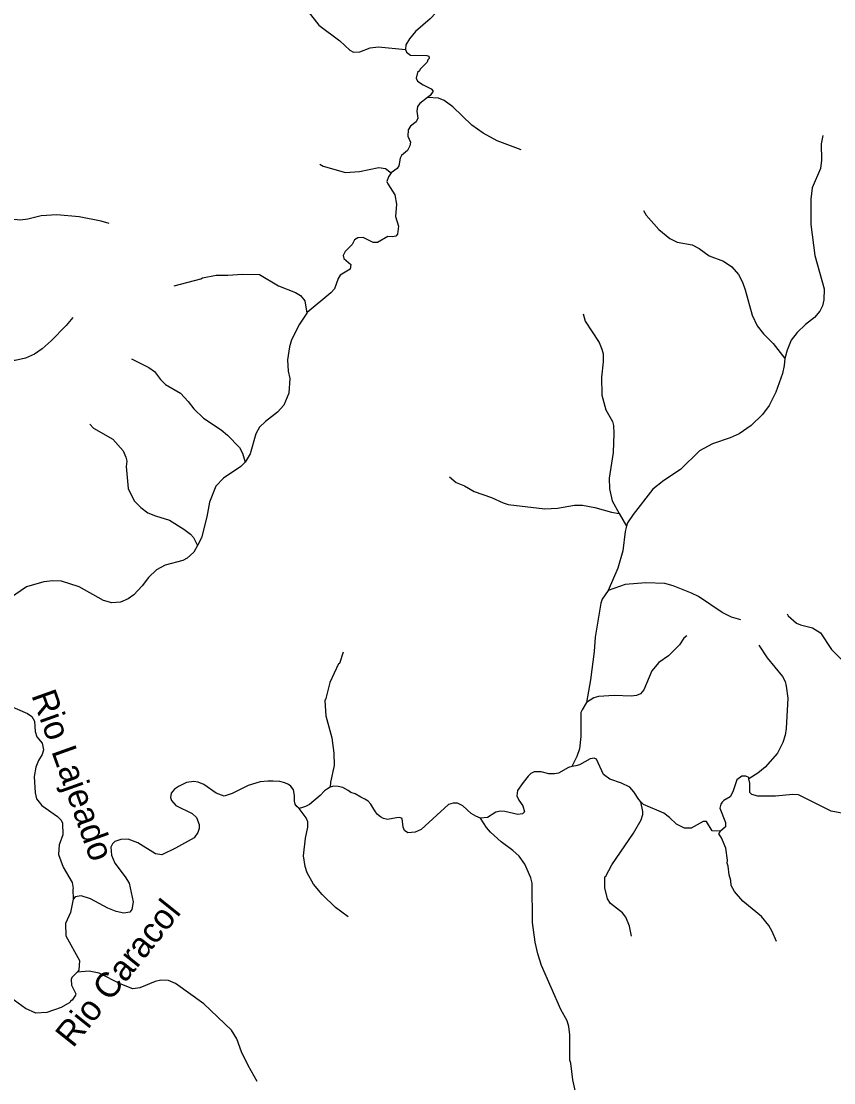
# Model space of a CAD drawing. Extents: x 280.4 to 335.6, y 8893.9 to 8949.5.
# Drawn here: x 309.86 to 316.37, y 8901.25 to 8909.74 of the extents above; entities that cross this region are included whole.
import ezdxf
from ezdxf.enums import TextEntityAlignment as Align

# ---------------------------------------------------------------- set-up
doc = ezdxf.new("R2010")
doc.units = 0
doc.header["$LTSCALE"] = 0.064
doc.layers.add('61', color=7, linetype='Continuous')
doc.layers.add('7', color=7, linetype='Continuous', lineweight=25)

msp = doc.modelspace()

# ---------------------------------------------------------------- linework, layer by layer
at = {"layer": '7'}
msp.add_line((314.649, 8905.8038), (314.7074, 8905.7013), dxfattribs=at)
for points in [[(313.2777, 8909.9961), (313.275, 8909.978), (313.25, 8909.9355), (313.2249, 8909.9078), (313.2207, 8909.8915), (313.2144, 8909.8897), (313.211, 8909.8641), (313.1829, 8909.8126), (313.136, 8909.7596), (313.0193, 8909.6603), (312.969, 8909.6008), (312.9395, 8909.5529), (312.9378, 8909.5154)], [(312.1598, 8909.8191), (312.2456, 8909.7111), (312.4115, 8909.5851), (312.4922, 8909.5097), (312.5214, 8909.4927), (312.5734, 8909.4957), (312.6547, 8909.5275), (312.7218, 8909.5356), (312.9378, 8909.5154)], [(312.9378, 8909.5154), (312.9461, 8909.495), (312.9781, 8909.4687), (313.1088, 8909.4684), (313.1247, 8909.4612), (313.1277, 8909.4436), (313.1171, 8909.4331), (313.1109, 8909.4129), (313.0562, 8909.3593), (313.0505, 8909.3434), (313.0335, 8909.3316), (313.0228, 8909.2862), (313.0354, 8909.2611), (313.0801, 8909.2318), (313.1433, 8909.2017), (313.1595, 8909.1827), (313.1356, 8909.1478), (313.1144, 8909.1311)], [(313.1144, 8909.1311), (313.0524, 8909.0822), (313.034, 8909.0592), (313.029, 8909.0222), (313.0361, 8908.9649), (313.0222, 8908.9375), (312.9779, 8908.901), (312.9585, 8908.8716), (312.9571, 8908.8208), (312.9776, 8908.7732), (312.9727, 8908.7456), (312.9548, 8908.7074), (312.9067, 8908.6682), (312.8951, 8908.6469), (312.8839, 8908.5857), (312.8727, 8908.5645), (312.8227, 8908.5286)], [(313.8627, 8908.7139), (313.6724, 8908.7853), (313.5604, 8908.846), (313.4682, 8908.9092), (313.3167, 8909.0574), (313.2469, 8909.1074), (313.201, 8909.1247), (313.1144, 8909.1311)], [(316.2781, 8908.8275), (316.2638, 8908.761), (316.2673, 8908.6297), (316.2591, 8908.5626), (316.1926, 8908.408), (316.181, 8908.3176), (316.1826, 8908.114), (316.2152, 8907.8667), (316.2881, 8907.5998), (316.2867, 8907.5134), (316.275, 8907.4655), (316.2536, 8907.4218), (316.2112, 8907.3719), (316.1408, 8907.3161), (316.0739, 8907.2518), (316.0236, 8907.1889), (315.9918, 8907.1089), (315.9735, 8907.043)], [(312.2524, 8908.5976), (312.279, 8908.5829), (312.4588, 8908.5317), (312.5708, 8908.5392), (312.7257, 8908.5713), (312.7772, 8908.5643), (312.8227, 8908.5286)], [(310.5652, 8908.1229), (310.502, 8908.1416), (310.325, 8908.1774), (310.1463, 8908.1938), (310.0229, 8908.1858), (309.9163, 8908.1592), (309.8559, 8908.1507), (309.6104, 8908.173), (309.5179, 8908.2148), (309.4827, 8908.2408), (309.434, 8908.2967), (309.3709, 8908.3975), (309.3356, 8908.439), (309.2745, 8908.4639), (309.2186, 8908.4753)], [(312.8227, 8908.5286), (312.8016, 8908.4955), (312.7896, 8908.4594), (312.7957, 8908.4405), (312.8528, 8908.3518), (312.8658, 8908.2773), (312.8593, 8908.1802), (312.8831, 8908.1024), (312.8733, 8908.0382), (312.8598, 8908.0207), (312.8353, 8908.0166), (312.7973, 8908.0205), (312.7137, 8907.9716), (312.6796, 8907.972), (312.6004, 8908.0123), (312.556, 8908.0084), (312.5296, 8907.9913), (312.5102, 8907.956), (312.456, 8907.8988), (312.4393, 8907.8666), (312.445, 8907.8431), (312.5006, 8907.7953), (312.4949, 8907.7577), (312.4153, 8907.7094), (312.3993, 8907.683), (312.3702, 8907.6013), (312.3416, 8907.5691)], [(314.842, 8908.2271), (314.8638, 8908.1901), (314.9651, 8908.0759), (315.0535, 8908.0024), (315.1136, 8907.975), (315.2336, 8907.9517), (315.2875, 8907.9231), (315.3698, 8907.8644), (315.4828, 8907.8223), (315.5502, 8907.7753), (315.6045, 8907.7141), (315.6356, 8907.6527), (315.6577, 8907.5916), (315.7127, 8907.3887), (315.7516, 8907.3045), (315.8046, 8907.2397), (315.8819, 8907.1639), (315.9735, 8907.043)], [(311.0857, 8907.6257), (311.3009, 8907.6806), (311.3141, 8907.6899), (311.424, 8907.7089), (311.5174, 8907.7093), (311.6333, 8907.7189), (311.7707, 8907.7142), (311.9222, 8907.6244), (312.0571, 8907.5714), (312.0964, 8907.5477), (312.1331, 8907.5037), (312.1481, 8907.4065)], [(312.3416, 8907.5691), (312.1511, 8907.411), (312.1481, 8907.4065)], [(310.2749, 8907.3713), (310.2211, 8907.3069), (310.1034, 8907.1859), (310.029, 8907.1199), (309.9678, 8907.0776), (309.8965, 8907.0448), (309.8143, 8907.0264), (309.696, 8907.0279), (309.6442, 8907.0197), (309.5777, 8906.9943), (309.5114, 8906.9493), (309.4331, 8906.9094), (309.3338, 8906.8823), (309.2379, 8906.867), (309.2034, 8906.8536), (309.1728, 8906.8331), (309.1542, 8906.811), (309.0991, 8906.6845)], [(312.1481, 8907.4065), (312.0888, 8907.3186), (312.0252, 8907.1927), (312.0089, 8907.1374), (311.9927, 8907.0319), (311.999, 8906.9424), (312.0117, 8906.8833), (312.0035, 8906.7649), (311.9637, 8906.6698), (311.9138, 8906.615), (311.8172, 8906.539), (311.7703, 8906.4938), (311.7415, 8906.4394), (311.6952, 8906.2802), (311.6537, 8906.2127)], [(314.3612, 8907.401), (314.3748, 8907.3406), (314.4873, 8907.1703), (314.5107, 8907.1188), (314.5192, 8907.0806), (314.5192, 8907.0168), (314.5066, 8906.8944), (314.5094, 8906.7493), (314.5428, 8906.6329), (314.5945, 8906.5386), (314.6025, 8906.5059), (314.6057, 8906.4443), (314.5993, 8906.2899), (314.5689, 8906.0869), (314.5708, 8905.9996), (314.5921, 8905.9037), (314.649, 8905.8038)], [(310.7438, 8907.0412), (310.8845, 8906.9711), (310.93, 8906.9387), (310.9779, 8906.8753), (311.018, 8906.8362), (311.138, 8906.7661), (311.1998, 8906.6997), (311.244, 8906.6415), (311.3203, 8906.5646), (311.4615, 8906.473), (311.5132, 8906.4293), (311.6096, 8906.3309), (311.633, 8906.2853), (311.6537, 8906.2127)], [(315.9735, 8907.043), (315.9683, 8906.9863), (315.9552, 8906.9241), (315.9029, 8906.7728), (315.8487, 8906.6672), (315.7943, 8906.5948), (315.7038, 8906.5062), (315.6075, 8906.4399), (315.5372, 8906.4077), (315.395, 8906.3607), (315.2903, 8906.3035), (315.1392, 8906.1559), (315.0056, 8906.0684), (314.9186, 8905.9975), (314.7593, 8905.7965), (314.7147, 8905.7289), (314.7074, 8905.7013)], [(310.4106, 8906.5168), (310.4401, 8906.4855), (310.5952, 8906.3973), (310.6772, 8906.3035), (310.6998, 8906.2552), (310.7066, 8906.2226), (310.702, 8906.1786), (310.7177, 8906.0029), (310.7655, 8905.904), (310.8197, 8905.8499), (310.8756, 8905.8098), (310.9365, 8905.7844), (311.0496, 8905.7497), (311.1647, 8905.6777), (311.2184, 8905.6366), (311.2419, 8905.61), (311.272, 8905.5461)], [(311.6537, 8906.2127), (311.6207, 8906.1782), (311.4811, 8906.0866), (311.4188, 8906.0207), (311.3687, 8905.895), (311.3487, 8905.7762), (311.3063, 8905.6079), (311.272, 8905.5461)], [(313.291, 8906.0962), (313.3447, 8906.0525), (313.4113, 8906.0242), (313.4888, 8905.9792), (313.6251, 8905.9303), (313.7188, 8905.8876), (313.7604, 8905.8761), (314.054, 8905.8397), (314.1554, 8905.8462), (314.2897, 8905.8686), (314.3555, 8905.8686), (314.4522, 8905.8524), (314.5865, 8905.8142), (314.649, 8905.8038)], [(314.7074, 8905.7013), (314.6965, 8905.6604), (314.6773, 8905.5039), (314.6376, 8905.3658), (314.5615, 8905.1867)], [(311.272, 8905.5461), (311.2431, 8905.494), (311.1903, 8905.4468), (311.1561, 8905.428), (311.0138, 8905.3903), (310.9462, 8905.3522), (310.8807, 8905.2904), (310.8309, 8905.2235), (310.7649, 8905.1526), (310.7197, 8905.1193), (310.658, 8905.0928), (310.5876, 8905.0898), (310.5197, 8905.1067), (310.3261, 8905.2176), (310.1853, 8905.2607), (310.1143, 8905.2654), (310.0446, 8905.2575), (309.9055, 8905.2166), (309.7757, 8905.1296)], [(315.6222, 8904.9533), (315.5477, 8904.9739), (315.4736, 8905.0108), (315.282, 8905.1393), (315.2281, 8905.1671), (315.0798, 8905.2254), (315.0126, 8905.2429), (314.8606, 8905.2496), (314.6949, 8905.2342), (314.5615, 8905.1867)], [(314.5615, 8905.1867), (314.5124, 8905.118), (314.5005, 8905.0853), (314.4554, 8904.8139), (314.4489, 8904.7001), (314.42, 8904.4717), (314.3868, 8904.2912)], [(315.994, 8905.0002), (316.0004, 8904.9832), (316.0687, 8904.9259), (316.0988, 8904.9124), (316.1953, 8904.8897), (316.2593, 8904.8497), (316.3487, 8904.7142), (316.568, 8904.4915), (316.6468, 8904.3959), (316.7017, 8904.3601), (316.8153, 8904.3157), (316.8702, 8904.2836), (316.9577, 8904.2101), (316.9931, 8904.1468), (317.0078, 8904.0814), (317.0066, 8904.0327), (317.0143, 8904.006)], [(315.1886, 8904.8257), (315.1664, 8904.8066), (315.1321, 8904.7528), (315.0437, 8904.6632), (314.9664, 8904.6121), (314.9091, 8904.5447), (314.8465, 8904.3927), (314.8196, 8904.3603), (314.7866, 8904.3484), (314.744, 8904.3429), (314.6073, 8904.346), (314.4838, 8904.3401), (314.4455, 8904.3283), (314.3868, 8904.2912)], [(315.7651, 8904.7504), (315.8329, 8904.6485), (315.9546, 8904.4991), (315.9761, 8904.4579), (315.9861, 8904.4206), (315.997, 8904.3245), (315.9857, 8904.0838), (315.9764, 8904.0285), (315.9571, 8903.9702), (315.9142, 8903.8845), (315.8161, 8903.773), (315.7581, 8903.7266), (315.6873, 8903.6812)], [(312.4392, 8904.693), (312.4094, 8904.6023), (312.4015, 8904.5993), (312.3318, 8904.4506), (312.3014, 8904.3234), (312.2917, 8904.3053), (312.2998, 8904.1846), (312.3475, 8904.0085), (312.3636, 8903.8854), (312.3667, 8903.7876), (312.3375, 8903.6544), (312.3345, 8903.614)], [(314.3868, 8904.2912), (314.3527, 8904.2319), (314.3423, 8904.2102), (314.3402, 8904.1827), (314.3402, 8904.0196), (314.332, 8903.9215), (314.3098, 8903.8582), (314.2689, 8903.7795)], [(309.7534, 8904.2732), (309.9135, 8904.2036), (309.9485, 8904.1792), (309.9679, 8904.1422), (309.9745, 8904.059), (309.9882, 8904.0163), (310.0313, 8903.9649), (310.0396, 8903.9113), (310.0295, 8903.8747), (310.0006, 8903.8278), (309.9804, 8903.7743), (309.9649, 8903.6999), (309.973, 8903.5688), (309.9857, 8903.5195), (310.0265, 8903.467), (310.1517, 8903.38), (310.1817, 8903.3493), (310.1917, 8903.3264), (310.1949, 8903.2321), (310.1672, 8903.1519), (310.1601, 8903.0763), (310.1985, 8902.9748), (310.2703, 8902.85), (310.2794, 8902.8037), (310.2749, 8902.797), (310.2791, 8902.7174)], [(314.2689, 8903.7795), (314.2425, 8903.7721), (314.1626, 8903.7259), (314.1316, 8903.7192), (314.084, 8903.7192), (314.025, 8903.7367), (313.9686, 8903.7368), (313.9418, 8903.7241), (313.9187, 8903.7017), (313.8788, 8903.6515), (313.8343, 8903.5869), (313.8288, 8903.5451), (313.8457, 8903.5095), (313.8779, 8903.4648), (313.8904, 8903.4153), (313.8755, 8903.3993), (313.8363, 8903.3964), (313.7333, 8903.4198), (313.6973, 8903.4215), (313.6622, 8903.4134), (313.5948, 8903.3722), (313.5391, 8903.3653)], [(314.8207, 8903.4976), (314.8051, 8903.5138), (314.7656, 8903.5767), (314.7336, 8903.6148), (314.6665, 8903.6471), (314.5748, 8903.678), (314.522, 8903.7157), (314.4677, 8903.8371), (314.4489, 8903.8453), (314.4149, 8903.841), (314.33, 8903.7924), (314.3019, 8903.7839), (314.2689, 8903.7795)], [(315.6873, 8903.6812), (315.6855, 8903.6923), (315.6631, 8903.7028), (315.6311, 8903.7013), (315.5898, 8903.6713), (315.5574, 8903.5775), (315.5366, 8903.5357), (315.4854, 8903.5062), (315.4739, 8903.4933), (315.4606, 8903.4783), (315.4537, 8903.4458), (315.4992, 8903.3321), (315.498, 8903.2962), (315.4595, 8903.262)], [(312.0858, 8903.4441), (312.0675, 8903.4595), (312.054, 8903.4779), (312.0492, 8903.502), (312.0494, 8903.5476), (312.0405, 8903.5917), (312.0211, 8903.6214), (312.0005, 8903.6349), (311.972, 8903.6487), (311.9333, 8903.6586), (311.8794, 8903.6622), (311.8374, 8903.6631), (311.7743, 8903.6565), (311.679, 8903.6279), (311.5511, 8903.5624), (311.4866, 8903.5416), (311.4226, 8903.5659), (311.3231, 8903.6338), (311.2799, 8903.6532), (311.2443, 8903.6598), (311.1841, 8903.6505), (311.12, 8903.6187), (311.09, 8903.597), (311.0621, 8903.566), (311.0573, 8903.5312), (311.066, 8903.5082)], [(312.3345, 8903.614), (312.3126, 8903.5994), (312.291, 8903.5855), (312.255, 8903.5467), (312.1706, 8903.475), (312.1379, 8903.4586), (312.1148, 8903.4499), (312.0858, 8903.4441)], [(313.5391, 8903.3653), (313.5019, 8903.3805), (313.4647, 8903.4038), (313.3964, 8903.4649), (313.355, 8903.487), (313.3184, 8903.4851), (313.2833, 8903.4759), (313.0634, 8903.2759), (313.0167, 8903.2541), (312.9579, 8903.2479), (312.9303, 8903.2678), (312.9206, 8903.2934), (312.9117, 8903.3636), (312.8926, 8903.3704), (312.867, 8903.3688), (312.7937, 8903.3562), (312.7627, 8903.3628), (312.7388, 8903.3758), (312.7139, 8903.3949), (312.6977, 8903.4161), (312.6779, 8903.4524), (312.6599, 8903.4788), (312.6381, 8903.5019), (312.6117, 8903.5184), (312.5818, 8903.5338), (312.5345, 8903.5599), (312.4998, 8903.5724), (312.4785, 8903.5859), (312.4378, 8903.6099), (312.4004, 8903.6197), (312.3626, 8903.6215), (312.3345, 8903.614)], [(315.7579, 8903.5416), (315.7089, 8903.5539), (315.6944, 8903.572), (315.6931, 8903.6447), (315.6873, 8903.6812)], [(316.4437, 8903.4019), (316.3449, 8903.4218), (316.0842, 8903.5511), (316.0379, 8903.5559), (315.8987, 8903.5416), (315.7579, 8903.5416)], [(311.066, 8903.5082), (311.0987, 8903.4666), (311.2312, 8903.4041), (311.2666, 8903.3713), (311.2869, 8903.3151), (311.2871, 8903.2833), (311.2765, 8903.2514), (311.2471, 8903.2091), (311.0976, 8903.1245), (310.9891, 8903.0716), (310.9364, 8903.0798), (310.7946, 8903.1689), (310.7195, 8903.1976), (310.6584, 8903.195), (310.6129, 8903.1802), (310.5937, 8903.1614), (310.5795, 8903.1336), (310.585, 8903.0691), (310.6125, 8903.007), (310.6955, 8902.8954), (310.7258, 8902.8451), (310.7579, 8902.6964), (310.7481, 8902.635), (310.7319, 8902.6143), (310.6836, 8902.6046), (310.6219, 8902.6183), (310.5558, 8902.6448), (310.4156, 8902.7211), (310.3421, 8902.7449), (310.295, 8902.7352), (310.2791, 8902.7174)], [(312.4793, 8902.5772), (312.3773, 8902.6513), (312.2718, 8902.7556), (312.2021, 8902.838), (312.1514, 8902.9281), (312.1358, 8902.9782), (312.1205, 8903.0634), (312.1383, 8903.2064), (312.1572, 8903.2929), (312.1557, 8903.337), (312.1418, 8903.3679), (312.1192, 8903.4003), (312.0858, 8903.4441)], [(314.7459, 8902.4227), (314.7317, 8902.5021), (314.7012, 8902.573), (314.6759, 8902.6089), (314.579, 8902.6827), (314.5544, 8902.7202), (314.5323, 8902.8091), (314.5338, 8902.8977), (314.5413, 8902.9021), (314.5886, 8902.9925), (314.7632, 8903.2454), (314.8245, 8903.3522), (314.8373, 8903.3962), (314.8376, 8903.4199), (314.8207, 8903.4976)], [(315.4595, 8903.262), (315.3931, 8903.2649), (315.3485, 8903.3386), (315.3196, 8903.3399), (315.2257, 8903.2862), (315.1703, 8903.2865), (315.1073, 8903.3182), (315.0519, 8903.372), (315.0044, 8903.4053), (314.8424, 8903.475), (314.8207, 8903.4976)], [(314.3162, 8901.0901), (314.2764, 8901.2731), (314.2619, 8901.4067), (314.2541, 8901.4306), (314.2521, 8901.6335), (314.2444, 8901.6985), (314.2307, 8901.7454), (314.1801, 8901.8358), (314.0271, 8902.188), (313.9963, 8902.2805), (313.9759, 8902.3735), (313.9533, 8902.5315), (313.953, 8902.845), (313.9418, 8902.8897), (313.894, 8902.9978), (313.8466, 8903.063), (313.7965, 8903.1081), (313.7048, 8903.1761), (313.6184, 8903.2544), (313.5855, 8903.2922), (313.5391, 8903.3653)], [(315.9081, 8902.3794), (315.8735, 8902.4602), (315.8454, 8902.5063), (315.787, 8902.5793), (315.638, 8902.7029), (315.5715, 8902.7784), (315.544, 8902.8263), (315.5425, 8902.8679), (315.5285, 8902.9115), (315.5205, 8902.9823), (315.5113, 8903.0059), (315.5141, 8903.0291), (315.5012, 8903.1257), (315.4683, 8903.2076), (315.4459, 8903.2395), (315.4595, 8903.262)], [(310.2791, 8902.7174), (310.2573, 8902.6116), (310.2173, 8902.5237), (310.2188, 8902.4251), (310.3287, 8902.2277), (310.3244, 8902.1484), (310.3098, 8902.1337)], [(310.3098, 8902.1337), (310.2674, 8902.0911), (310.2613, 8902.0756), (310.2643, 8902.0308), (310.3003, 8901.9612), (310.298, 8901.9488), (310.2708, 8901.9085), (310.2556, 8901.9004), (310.2522, 8901.8914), (310.1828, 8901.8515), (310.0663, 8901.8111), (309.9802, 8901.8067), (309.8958, 8901.8439), (309.7805, 8901.9275)], [(311.7521, 8901.2592), (311.6792, 8901.3858), (311.6258, 8901.4953), (311.5882, 8901.5993), (311.5445, 8901.6701), (311.324, 8901.8802), (311.0974, 8902.0437), (311.0404, 8902.0675), (310.98, 8902.0704), (310.9335, 8902.0595), (310.8116, 8902.0076), (310.7554, 8901.9999), (310.6536, 8902.0393), (310.4854, 8902.1263), (310.4054, 8902.1422), (310.3098, 8902.1337)]]:
    msp.add_lwpolyline(points, dxfattribs=at)

# ---------------------------------------------------------------- texts
at = {"layer": '61'}
for s, rotation, p in [('Rio Lajeado', 289.654, (310.1818, 8903.6775)), ('Rio Caracol', 51.34, (310.7129, 8902.0665))]:
    msp.add_text(s, height=0.2, rotation=rotation, dxfattribs=at).set_placement(p, align=Align.CENTER)

doc.saveas('drawing.dxf')
